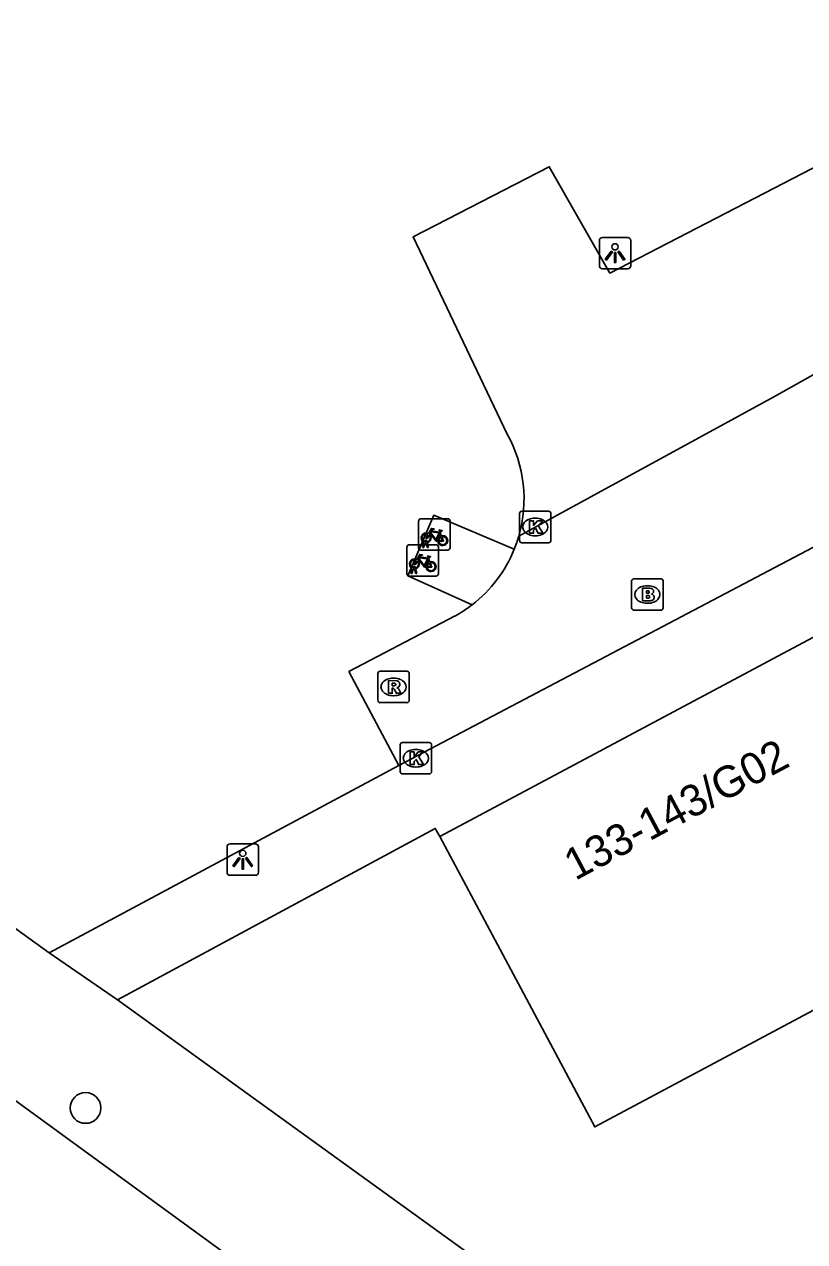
# Model space of a CAD drawing. Extents: x 159675 to 160530, y 382179 to 382901.
# Drawn here: x 159925.16 to 159949.99, y 382322.15 to 382360.88 of the extents above; entities that cross this region are included whole.
import ezdxf

# ---------------------------------------------------------------- set-up
doc = ezdxf.new("R2010")
doc.units = 0
for name, color, linetype in [('IMGEO_Boom', 7, 'Continuous'), ('IMGEO_Brandkraan', 7, 'Continuous'), ('IMGEO_Fietsenrek', 7, 'Continuous'), ('IMGEO_Groenvoorziening', 7, 'Continuous'), ('IMGEO_Kolk', 7, 'Continuous'), ('IMGEO_Lichtpunt', 7, 'Continuous'), ('IMGEO_Pand', 7, 'Continuous'), ('IMGEO_Pand_nummerreeks', 7, 'Continuous'), ('IMGEO_Parkeervlak_open', 7, 'Continuous'), ('IMGEO_Rijbaan_lokaal_open', 7, 'Continuous'), ('IMGEO_Rioolput', 7, 'Continuous'), ('IMGEO_Voetpad_open', 7, 'Continuous')]:
    doc.layers.add(name, color=color, linetype=linetype)

msp = doc.modelspace()

# ---------------------------------------------------------------- linework, layer by layer
at = {"layer": 'IMGEO_Boom'}
msp.add_circle((159927.112, 382326.403), 0.489, dxfattribs=at)
at = {"layer": 'IMGEO_Brandkraan'}
for p, q in [((159944.561, 382343.238), (159945.413, 382343.238)), ((159944.486, 382342.312), (159944.486, 382343.164)), ((159944.974, 382343.018), (159944.999, 382343.018)), ((159945.487, 382343.164), (159945.487, 382342.312)), ((159944.997, 382342.458), (159944.972, 382342.458)), ((159945.413, 382342.238), (159944.561, 382342.238))]:
    msp.add_line(p, q, dxfattribs=at)
for points in [[(159944.561, 382343.238), (159945.413, 382343.238)], [(159944.486, 382342.312), (159944.486, 382343.164)], [(159944.834, 382342.938), (159944.834, 382342.538), (159945.047, 382342.538)], [(159945.065, 382342.938), (159944.834, 382342.938)], [(159945.013, 382342.857), (159944.959, 382342.857), (159944.959, 382342.781)], [(159945.487, 382343.164), (159945.487, 382342.312)], [(159944.959, 382342.781), (159945.012, 382342.781)], [(159945.021, 382342.705), (159944.959, 382342.705), (159944.959, 382342.624)], [(159944.959, 382342.624), (159945.021, 382342.624)], [(159945.413, 382342.238), (159944.561, 382342.238)]]:
    msp.add_lwpolyline(points, dxfattribs=at)
for centre, radius, start, end in [((159944.563, 382343.162), 0.0765, 91.552, 178.448), ((159944.563, 382343.162), 0.0765, 91.552, 178.448), ((159945.411, 382343.162), 0.0765, 1.552, 88.448), ((159945.411, 382343.162), 0.0765, 1.552, 88.448), ((159945.014, 382342.819), 0.0379, 267.8285, 90.9355), ((159945.069, 382342.793), 0.145, 59.4692, 91.5367), ((159945.094, 382342.84), 0.0922, 285.5137, 58.1501), ((159945.022, 382342.664), 0.0404, 269.8759, 90.5077), ((159945.053, 382342.789), 0.251, 268.6676, 293.5347), ((159945.099, 382342.648), 0.105, 301.3115, 78.989), ((159944.563, 382342.314), 0.0765, 181.552, 268.448), ((159944.563, 382342.314), 0.0765, 181.552, 268.448), ((159945.411, 382342.314), 0.0765, 271.552, 358.448), ((159945.411, 382342.314), 0.0765, 271.552, 358.448)]:
    msp.add_arc(centre, radius, start, end, dxfattribs=at)
for centre, major_axis, ratio, start_param, end_param in [((159944.973, 382342.738), (-0.387, 0.002), 0.722429, 4.712389, 7.853982), ((159944.998, 382342.738), (-0.39, 0.002), 0.717154, 1.570796, 4.712389)]:
    msp.add_ellipse(centre, major_axis=major_axis, ratio=ratio, start_param=start_param, end_param=end_param, dxfattribs=at)
at = {"layer": 'IMGEO_Fietsenrek'}
for p, q in [((159937.783, 382345.15), (159938.624, 382345.15)), ((159938.624, 382345.15), (159937.783, 382345.15)), ((159937.708, 382344.225), (159937.708, 382345.066)), ((159937.708, 382345.066), (159937.708, 382344.225)), ((159938.708, 382345.075), (159938.708, 382344.234)), ((159938.708, 382344.234), (159938.708, 382345.075)), ((159937.835, 382344.234), (159937.874, 382344.394)), ((159937.904, 382344.382), (159937.869, 382344.234)), ((159937.946, 382344.406), (159937.945, 382344.41)), ((159937.987, 382344.234), (159937.953, 382344.376)), ((159937.977, 382344.417), (159937.978, 382344.41)), ((159937.985, 382344.38), (159938.02, 382344.234)), ((159938.395, 382344.699), (159938.431, 382344.604)), ((159937.337, 382343.398), (159937.337, 382344.239)), ((159937.337, 382344.239), (159937.337, 382343.398)), ((159937.412, 382344.323), (159938.253, 382344.323)), ((159938.253, 382344.323), (159937.412, 382344.323)), ((159938.633, 382344.15), (159937.792, 382344.15)), ((159937.792, 382344.15), (159938.633, 382344.15)), ((159937.869, 382344.234), (159937.835, 382344.234)), ((159938.02, 382344.234), (159937.987, 382344.234)), ((159938.337, 382344.248), (159938.337, 382343.407)), ((159938.337, 382343.407), (159938.337, 382344.248)), ((159937.575, 382343.579), (159937.574, 382343.583)), ((159937.606, 382343.59), (159937.607, 382343.583)), ((159938.024, 382343.872), (159938.06, 382343.777)), ((159938.262, 382343.323), (159937.421, 382343.323)), ((159937.421, 382343.323), (159938.262, 382343.323)), ((159937.464, 382343.407), (159937.503, 382343.567)), ((159937.498, 382343.407), (159937.464, 382343.407)), ((159937.533, 382343.555), (159937.498, 382343.407)), ((159937.616, 382343.407), (159937.582, 382343.549)), ((159937.614, 382343.553), (159937.649, 382343.407)), ((159937.649, 382343.407), (159937.616, 382343.407))]:
    msp.add_line(p, q, dxfattribs=at)
for points in [[(159938.021, 382344.676), (159938.116, 382344.84), (159938.202, 382344.826), (159938.204, 382344.817), (159938.148, 382344.806), (159938.121, 382344.761), (159938.377, 382344.72)], [(159938.364, 382344.695), (159938.107, 382344.736), (159938.09, 382344.707), (159938.257, 382344.487), (159938.364, 382344.695)], [(159938.377, 382344.72), (159938.402, 382344.769), (159938.396, 382344.773), (159938.373, 382344.777), (159938.361, 382344.784), (159938.36, 382344.787), (159938.362, 382344.792), (159938.457, 382344.777), (159938.459, 382344.767), (159938.449, 382344.754), (159938.437, 382344.748), (159938.423, 382344.754), (159938.395, 382344.699)], [(159938.042, 382344.624), (159937.99, 382344.534), (159937.95, 382344.509), (159937.951, 382344.556), (159938.006, 382344.65)], [(159938.317, 382344.432), (159938.267, 382344.432), (159938.076, 382344.683), (159938.057, 382344.651)], [(159938.412, 382344.597), (159938.382, 382344.674), (159938.273, 382344.456), (159938.316, 382344.456)], [(159938.346, 382344.456), (159938.466, 382344.455), (159938.422, 382344.569)], [(159938.442, 382344.576), (159938.497, 382344.431), (159938.347, 382344.431)], [(159937.65, 382343.849), (159937.745, 382344.013), (159937.831, 382343.999), (159937.833, 382343.99), (159937.777, 382343.979), (159937.75, 382343.934), (159938.006, 382343.893)], [(159938.006, 382343.893), (159938.031, 382343.942), (159938.025, 382343.946), (159938.002, 382343.95), (159937.99, 382343.957), (159937.989, 382343.96), (159937.991, 382343.965), (159938.086, 382343.95), (159938.088, 382343.94), (159938.078, 382343.927), (159938.066, 382343.921), (159938.052, 382343.927), (159938.024, 382343.872)], [(159937.671, 382343.797), (159937.619, 382343.707), (159937.579, 382343.682), (159937.58, 382343.729), (159937.635, 382343.823)], [(159937.946, 382343.605), (159937.896, 382343.605), (159937.705, 382343.856), (159937.686, 382343.824)], [(159937.993, 382343.868), (159937.736, 382343.909), (159937.719, 382343.88), (159937.886, 382343.66), (159937.993, 382343.868)], [(159938.041, 382343.77), (159938.011, 382343.847), (159937.902, 382343.629), (159937.945, 382343.629)], [(159937.975, 382343.629), (159938.095, 382343.628), (159938.051, 382343.742)], [(159938.071, 382343.749), (159938.126, 382343.604), (159937.976, 382343.604)]]:
    msp.add_lwpolyline(points, dxfattribs=at)
for centre, radius, start, end in [((159937.786, 382345.072), 0.0779, 92.4484, 184.2845), ((159937.786, 382345.072), 0.0779, 92.4484, 184.2845), ((159938.63, 382345.072), 0.0779, 2.4484, 94.2845), ((159938.63, 382345.072), 0.0779, 2.4484, 94.2845), ((159937.948, 382344.535), 0.159, 62.6766, 242.1369), ((159937.948, 382344.535), 0.129, 63.3192, 238.903), ((159937.928, 382344.406), 0.0499, 12.8025, 158.6934), ((159937.948, 382344.535), 0.159, 253.9967, 271.7867), ((159937.928, 382344.406), 0.0174, 12.8025, 163.4502), ((159937.948, 382344.535), 0.129, 253.415, 269.0204), ((159937.948, 382344.535), 0.129, 283.6043, 43.4302), ((159937.948, 382344.535), 0.159, 283.5766, 46.6042), ((159938.475, 382344.451), 0.159, 113.3408, 178.3217), ((159938.475, 382344.451), 0.159, 187.0065, 105.7708), ((159938.475, 382344.451), 0.129, 113.923, 177.9556), ((159938.475, 382344.451), 0.129, 188.6715, 104.5883), ((159937.415, 382344.245), 0.0779, 92.4484, 184.2845), ((159937.415, 382344.245), 0.0779, 92.4484, 184.2845), ((159937.786, 382344.228), 0.0779, 182.4484, 274.2845), ((159937.786, 382344.228), 0.0779, 182.4484, 274.2845), ((159938.259, 382344.245), 0.0779, 2.4484, 94.2845), ((159938.259, 382344.245), 0.0779, 2.4484, 94.2845), ((159938.63, 382344.228), 0.0779, 272.4484, 4.2845), ((159938.63, 382344.228), 0.0779, 272.4484, 4.2845), ((159937.577, 382343.708), 0.159, 62.6766, 242.1369), ((159937.577, 382343.708), 0.129, 63.3192, 238.903), ((159937.557, 382343.579), 0.0499, 12.8025, 158.6934), ((159937.557, 382343.579), 0.0174, 12.8025, 163.4502), ((159937.577, 382343.708), 0.129, 253.415, 269.0204), ((159937.577, 382343.708), 0.129, 283.6043, 43.4302), ((159937.577, 382343.708), 0.159, 283.5766, 46.6042), ((159938.104, 382343.624), 0.159, 113.3408, 178.3217), ((159938.104, 382343.624), 0.159, 187.0065, 105.7708), ((159938.104, 382343.624), 0.129, 113.923, 177.9556), ((159938.104, 382343.624), 0.129, 188.6715, 104.5883), ((159937.415, 382343.401), 0.0779, 182.4484, 274.2845), ((159937.415, 382343.401), 0.0779, 182.4484, 274.2845), ((159937.577, 382343.708), 0.159, 253.9967, 271.7867), ((159938.259, 382343.401), 0.0779, 272.4484, 4.2845), ((159938.259, 382343.401), 0.0779, 272.4484, 4.2845)]:
    msp.add_arc(centre, radius, start, end, dxfattribs=at)
at = {"layer": 'IMGEO_Groenvoorziening'}
msp.add_lwpolyline([(159939.411, 382342.411), (159937.363, 382343.336), (159938.191, 382345.258), (159940.753, 382344.183)], dxfattribs=at)
at = {"layer": 'IMGEO_Kolk'}
for p, q in [((159940.918, 382344.46), (159940.918, 382345.312)), ((159940.993, 382345.386), (159941.845, 382345.386)), ((159941.406, 382345.166), (159941.431, 382345.166)), ((159941.919, 382345.312), (159941.919, 382344.46)), ((159941.845, 382344.386), (159940.993, 382344.386)), ((159941.429, 382344.606), (159941.404, 382344.606)), ((159937.121, 382337.102), (159937.121, 382337.954)), ((159937.196, 382338.028), (159938.048, 382338.028)), ((159937.609, 382337.808), (159937.634, 382337.808)), ((159938.122, 382337.954), (159938.122, 382337.102)), ((159938.048, 382337.028), (159937.196, 382337.028)), ((159937.632, 382337.248), (159937.607, 382337.248))]:
    msp.add_line(p, q, dxfattribs=at)
for points in [[(159940.918, 382344.46), (159940.918, 382345.312)], [(159940.993, 382345.386), (159941.845, 382345.386)], [(159941.919, 382345.312), (159941.919, 382344.46)], [(159941.239, 382345.086), (159941.362, 382345.086), (159941.362, 382344.935), (159941.492, 382345.086), (159941.656, 382345.086), (159941.51, 382344.935), (159941.663, 382344.686), (159941.511, 382344.686), (159941.426, 382344.85), (159941.362, 382344.783), (159941.362, 382344.686), (159941.239, 382344.686), (159941.239, 382345.086)], [(159941.845, 382344.386), (159940.993, 382344.386)], [(159937.121, 382337.102), (159937.121, 382337.954)], [(159937.196, 382338.028), (159938.048, 382338.028)], [(159938.122, 382337.954), (159938.122, 382337.102)], [(159937.442, 382337.728), (159937.565, 382337.728), (159937.565, 382337.577), (159937.695, 382337.728), (159937.859, 382337.728), (159937.713, 382337.577), (159937.866, 382337.328), (159937.714, 382337.328), (159937.629, 382337.492), (159937.565, 382337.425), (159937.565, 382337.328), (159937.442, 382337.328), (159937.442, 382337.728)], [(159938.048, 382337.028), (159937.196, 382337.028)]]:
    msp.add_lwpolyline(points, dxfattribs=at)
for centre, start, end in [((159940.995, 382345.31), 91.552, 178.448), ((159940.995, 382345.31), 91.552, 178.448), ((159941.843, 382345.31), 1.552, 88.448), ((159941.843, 382345.31), 1.552, 88.448), ((159940.995, 382344.462), 181.552, 268.448), ((159940.995, 382344.462), 181.552, 268.448), ((159941.843, 382344.462), 271.552, 358.448), ((159941.843, 382344.462), 271.552, 358.448), ((159937.198, 382337.952), 91.552, 178.448), ((159937.198, 382337.952), 91.552, 178.448), ((159938.046, 382337.952), 1.552, 88.448), ((159938.046, 382337.952), 1.552, 88.448), ((159937.198, 382337.104), 181.552, 268.448), ((159937.198, 382337.104), 181.552, 268.448), ((159938.046, 382337.104), 271.552, 358.448), ((159938.046, 382337.104), 271.552, 358.448)]:
    msp.add_arc(centre, 0.0765, start, end, dxfattribs=at)
for centre, major_axis, ratio, start_param, end_param in [((159941.405, 382344.886), (-0.387, 0.002), 0.722429, 4.712389, 7.853982), ((159941.43, 382344.886), (-0.39, 0.002), 0.717154, 1.570796, 4.712389), ((159937.608, 382337.528), (-0.387, 0.002), 0.722429, 4.712389, 7.853982), ((159937.633, 382337.528), (-0.39, 0.002), 0.717154, 1.570796, 4.712389)]:
    msp.add_ellipse(centre, major_axis=major_axis, ratio=ratio, start_param=start_param, end_param=end_param, dxfattribs=at)
at = {"layer": 'IMGEO_Lichtpunt'}
for p, q in [((159944.362, 382354.097), (159943.554, 382354.097)), ((159944.362, 382354.097), (159943.554, 382354.097)), ((159943.46, 382354.002), (159943.46, 382353.195)), ((159943.46, 382354.002), (159943.46, 382353.195)), ((159944.456, 382353.195), (159944.456, 382354.002)), ((159944.456, 382353.195), (159944.456, 382354.002)), ((159943.554, 382353.101), (159944.362, 382353.101)), ((159943.554, 382353.101), (159944.362, 382353.101)), ((159931.615, 382334.708), (159931.615, 382333.901)), ((159931.615, 382334.708), (159931.615, 382333.901)), ((159932.517, 382334.803), (159931.709, 382334.803)), ((159932.517, 382334.803), (159931.709, 382334.803)), ((159932.611, 382333.901), (159932.611, 382334.708)), ((159932.611, 382333.901), (159932.611, 382334.708)), ((159931.709, 382333.807), (159932.517, 382333.807)), ((159931.709, 382333.807), (159932.517, 382333.807))]:
    msp.add_line(p, q, dxfattribs=at)
for points in [[(159943.834, 382353.666), (159943.873, 382353.638), (159943.685, 382353.376), (159943.647, 382353.403), (159943.834, 382353.666)], [(159944.046, 382353.638), (159944.084, 382353.665), (159944.271, 382353.403), (159944.232, 382353.375), (159944.046, 382353.638)], [(159943.936, 382353.618), (159943.983, 382353.618), (159943.983, 382353.296), (159943.936, 382353.296), (159943.936, 382353.618)], [(159931.989, 382334.372), (159932.028, 382334.344), (159931.84, 382334.082), (159931.802, 382334.109), (159931.989, 382334.372)], [(159932.091, 382334.324), (159932.138, 382334.324), (159932.138, 382334.002), (159932.091, 382334.002), (159932.091, 382334.324)], [(159932.201, 382334.344), (159932.239, 382334.371), (159932.426, 382334.109), (159932.387, 382334.081), (159932.201, 382334.344)]]:
    msp.add_lwpolyline(points, dxfattribs=at)
for centre in [(159943.959, 382353.8), (159932.114, 382334.506)]:
    msp.add_circle(centre, 0.0994, dxfattribs=at)
for centre, start, end in [((159943.554, 382354.002), 90, 180), ((159943.554, 382354.002), 90, 180), ((159944.362, 382354.002), 0, 90), ((159944.362, 382354.002), 0, 90), ((159943.554, 382353.195), 180, 270), ((159943.554, 382353.195), 180, 270), ((159944.362, 382353.195), 270, 0), ((159944.362, 382353.195), 270, 360), ((159931.709, 382334.708), 90, 180), ((159931.709, 382334.708), 90, 180), ((159932.517, 382334.708), 0, 90), ((159932.517, 382334.708), 0, 90), ((159931.709, 382333.901), 180, 270), ((159931.709, 382333.901), 180, 270), ((159932.517, 382333.901), 270, 0), ((159932.517, 382333.901), 270, 360)]:
    msp.add_arc(centre, 0.0946, start, end, dxfattribs=at)
at = {"layer": 'IMGEO_Pand'}
for points in [[(159953.909, 382343.326), (159938.381, 382335.041)], [(159938.381, 382335.041), (159943.311, 382325.8), (159958.839, 382334.084)]]:
    msp.add_lwpolyline(points, dxfattribs=at)
at = {"layer": 'IMGEO_Parkeervlak_open'}
msp.add_lwpolyline([(159940.529, 382347.836), (159937.53, 382354.114), (159941.863, 382356.347), (159943.794, 382352.965), (159954.842, 382358.673), (159956.987, 382355.398)], dxfattribs=at)
msp.add_arc((159936.811, 382345.775), 4.252, 343.9316, 29.0012, dxfattribs=at)
at = {"layer": 'IMGEO_Rijbaan_lokaal_open'}
for points in [[(159937.083, 382337.299), (159950.454, 382344.344), (159985.984, 382363.33)], [(159959.456, 382354.877), (159949.034, 382349.036), (159940.896, 382344.598)], [(159887.605, 382353.798), (159890.6, 382351.611), (159893.393, 382349.55), (159896.667, 382347.174), (159905.175, 382340.999), (159920.932, 382329.502), (159937.537, 382317.412), (159953.332, 382305.907), (159982.528, 382284.68), (160000, 382271.92), (160015.743, 382260.43), (160017.531, 382259.139)], [(159937.083, 382337.299), (159935.493, 382340.283), (159938.868, 382342.054)]]:
    msp.add_lwpolyline(points, dxfattribs=at)
for centre, radius, start, end in [((159936.824, 382345.769), 4.237, 338.0177, 343.9567), ((159936.81, 382345.775), 4.253, 307.7121, 338.012), ((159936.794, 382345.8), 4.282, 298.9718, 307.6748)]:
    msp.add_arc(centre, radius, start, end, dxfattribs=at)
at = {"layer": 'IMGEO_Rioolput'}
for p, q in [((159936.411, 382339.371), (159936.411, 382340.223)), ((159936.486, 382340.297), (159937.338, 382340.297)), ((159937.412, 382340.223), (159937.412, 382339.371)), ((159936.899, 382340.077), (159936.924, 382340.077)), ((159936.922, 382339.517), (159936.897, 382339.517)), ((159937.338, 382339.297), (159936.486, 382339.297))]:
    msp.add_line(p, q, dxfattribs=at)
for points in [[(159936.411, 382339.371), (159936.411, 382340.223)], [(159936.486, 382340.297), (159937.338, 382340.297)], [(159937.412, 382340.223), (159937.412, 382339.371)], [(159937, 382339.995), (159936.748, 382339.997), (159936.748, 382339.597)], [(159936.748, 382339.597), (159936.872, 382339.597), (159936.872, 382339.759), (159936.883, 382339.759)], [(159936.926, 382339.916), (159936.872, 382339.916), (159936.872, 382339.835)], [(159936.872, 382339.835), (159936.924, 382339.835)], [(159936.93, 382339.73), (159937.001, 382339.597), (159937.141, 382339.597), (159937.076, 382339.723)], [(159937.338, 382339.297), (159936.486, 382339.297)]]:
    msp.add_lwpolyline(points, dxfattribs=at)
for centre, radius, start, end in [((159936.488, 382340.221), 0.0765, 91.552, 178.448), ((159936.488, 382340.221), 0.0765, 91.552, 178.448), ((159937.336, 382340.221), 0.0765, 1.552, 88.448), ((159937.336, 382340.221), 0.0765, 1.552, 88.448), ((159936.882, 382339.706), 0.0533, 26.0293, 88.6989), ((159936.908, 382340.024), 0.19, 274.7715, 282.9687), ((159936.932, 382339.82), 0.0964, 77.0061, 93.1865), ((159936.946, 382339.877), 0.0378, 276.6634, 79.6772), ((159936.999, 382339.885), 0.109, 350.3612, 89.416), ((159936.997, 382339.885), 0.112, 277.5842, 350.9817), ((159936.981, 382339.67), 0.108, 29.5134, 73.7905), ((159936.488, 382339.373), 0.0765, 181.552, 268.448), ((159936.488, 382339.373), 0.0765, 181.552, 268.448), ((159937.336, 382339.373), 0.0765, 271.552, 358.448), ((159937.336, 382339.373), 0.0765, 271.552, 358.448)]:
    msp.add_arc(centre, radius, start, end, dxfattribs=at)
for centre, major_axis, ratio, start_param, end_param in [((159936.898, 382339.797), (-0.387, 0.002), 0.722429, 4.712389, 7.853982), ((159936.923, 382339.797), (-0.39, 0.002), 0.717154, 1.570796, 4.712389)]:
    msp.add_ellipse(centre, major_axis=major_axis, ratio=ratio, start_param=start_param, end_param=end_param, dxfattribs=at)
at = {"layer": 'IMGEO_Voetpad_open'}
for points in [[(159925.951, 382331.335), (159899.107, 382350.689), (159896.041, 382352.9), (159893.426, 382354.811), (159888.032, 382358.712), (159894.018, 382367.057), (159897.322, 382368.812)], [(159925.951, 382331.335), (159937.083, 382337.299)], [(159928.126, 382329.843), (159938.238, 382335.298), (159938.381, 382335.041)], [(159928.126, 382329.843), (159925.951, 382331.335)], [(159964.599, 382303.191), (159949.672, 382314.284), (159928.126, 382329.843)]]:
    msp.add_lwpolyline(points, dxfattribs=at)

# ---------------------------------------------------------------- texts
at = {"layer": 'IMGEO_Pand_nummerreeks'}
msp.add_text('133-143/G02', height=1, rotation=28.0808, dxfattribs=at).set_placement((159942.689, 382333.622))

doc.saveas('drawing.dxf')
